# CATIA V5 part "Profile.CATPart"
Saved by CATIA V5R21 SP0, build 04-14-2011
Part number: Profile
Bounding box of the stored display mesh (mm): x -58.221 to 95.108, y -67.694 to 79.25, z 0 to 0
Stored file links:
  D:\CATIA V5R21 E-RESOURCES\CATIA-V5R21\catia-v5r21-prt\c16-catia-v5r20-prt\Point Curve Joint-(16-36)\CAT_V5R21_Profile.CATPart
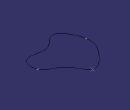
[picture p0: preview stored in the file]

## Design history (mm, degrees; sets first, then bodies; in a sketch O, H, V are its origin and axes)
Body1 (main body)
  Sketch1 on xy-plane, origin (0, 0, 0), H (1, 0, 0), V (0, 1, 0)
    spline S1 through (-56.936, -9.8228) (-36.2121, 48.255) (9.4222, 78.5932) (39.7622, 40.0274) (63.9393, 19.9693) (91.4937, -1.8468) (86.3206, -40.9294) (25.4678, -42.273) (-9.6787, -66.1719) (-56.936, -9.8228)
    point P1 (-56.936, -9.8228)
    point P2 (-56.936, -9.8228)
    coincidence: P1 P2
  Sketch2 on yz-plane, origin (0, 0, 0), H (0, 1, 0), V (0, 0, 1)
    line L1 (0, 84.1472) -> (0, 110.8669)
    point P1 (0, 84.1472)
    line L2 (0, 110.8669) -> (-22.6823, 110.8669)
    coincidence: P1 V
    vertical: L1 V
    horizontal: L2 H
  Point1: type OnCurve, Support Sketch1, RefPoint {extremum Reference Sketch1, Direction (1, 2, 3)}, Length 0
